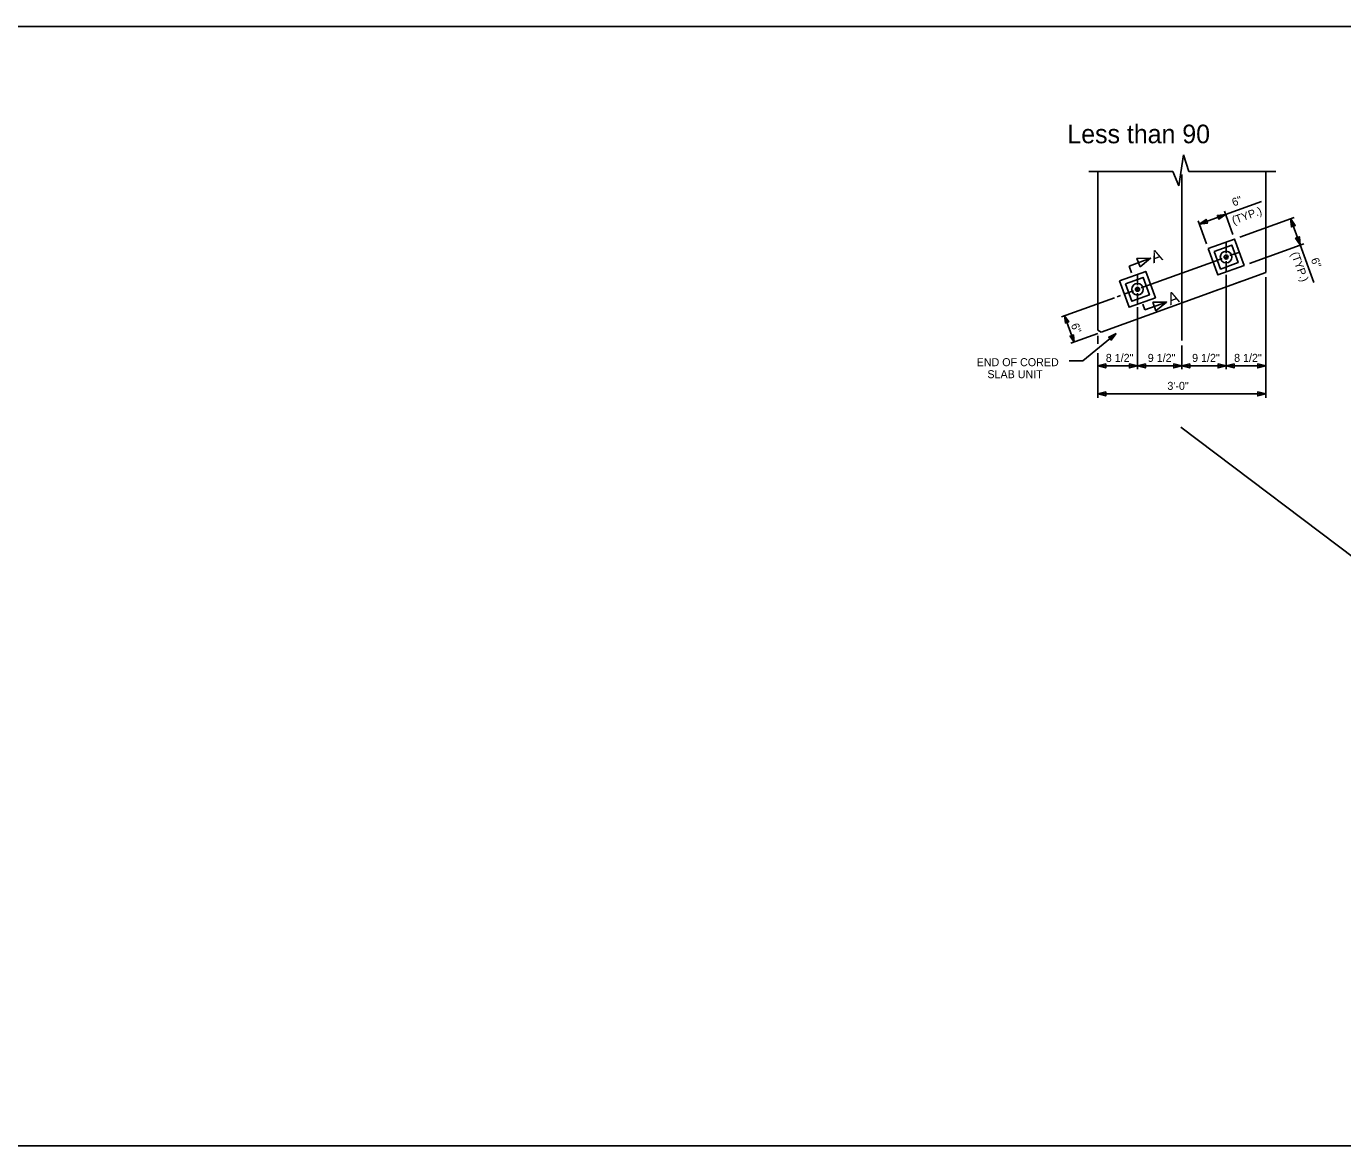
# Model space of a CAD drawing. Extents: x 0 to 177, y -1 to 130.
# Drawn here: x 125.78 to 149.29, y -0.86 to 19.14 of the extents above; entities that cross this region are included whole.
import ezdxf

# ---------------------------------------------------------------- set-up
doc = ezdxf.new("R2010")
doc.units = 0
for name, color, linetype in [('Arrowhead Terminators CELL', 7, 'Continuous'), ('Dimension Lines', 7, 'Continuous'), ('Mis Center Lines', 7, 'Continuous'), ('Plan Sheet', 7, 'Continuous'), ('Rebar Lines', 7, 'Continuous'), ('Structural Steel Lines', 7, 'Continuous'), ('Sup Concrete Girder Lines', 7, 'Continuous'), ('Sup Cored Slab Unit', 7, 'Continuous'), ('Text', 7, 'Continuous'), ('User Information Notes', 7, 'Continuous')]:
    doc.layers.add(name, color=color, linetype=linetype)

msp = doc.modelspace()

# ---------------------------------------------------------------- linework, layer by layer
at = {"layer": 'Arrowhead Terminators CELL'}
for points in [[(147.2, 15.773), (147.078, 15.69), (147.054, 15.757)], [(146.73, 15.602), (146.852, 15.684), (146.876, 15.617)], [(148.362, 15.699), (148.444, 15.577), (148.378, 15.552)], [(148.533, 15.229), (148.451, 15.35), (148.518, 15.375)], [(145.672, 14.837), (145.861, 14.991), (145.618, 14.988)], [(145.903, 14.205), (146.146, 14.208), (145.957, 14.054)], [(145.246, 13.647), (145.159, 13.529), (145.114, 13.584)], [(144.918, 13.068), (145.061, 13.104), (145.061, 13.033)], [(145.627, 13.068), (145.484, 13.033), (145.484, 13.104)], [(145.627, 13.068), (145.769, 13.104), (145.769, 13.033)], [(146.418, 13.068), (146.276, 13.033), (146.276, 13.104)], [(146.418, 13.068), (146.561, 13.104), (146.561, 13.033)], [(147.21, 13.068), (147.068, 13.033), (147.068, 13.104)], [(147.21, 13.068), (147.353, 13.104), (147.353, 13.033)], [(147.918, 13.068), (147.776, 13.033), (147.776, 13.104)], [(144.918, 12.568), (145.061, 12.604), (145.061, 12.533)], [(147.918, 12.568), (147.776, 12.533), (147.776, 12.604)]]:
    msp.add_lwpolyline(points, close=True, dxfattribs=at)
at = {"layer": 'Dimension Lines'}
for p, q in [((147.843, 16.007), (147.2, 15.773)), ((147.2, 15.773), (146.73, 15.602)), ((147.179, 15.83), (147.329, 15.418)), ((146.709, 15.659), (146.859, 15.247)), ((148.425, 15.721), (147.454, 15.368)), ((148.362, 15.699), (148.533, 15.229)), ((147.21, 15.272), (147.21, 15.084)), ((147.455, 15.102), (147.278, 15.038)), ((148.596, 15.252), (147.625, 14.898)), ((148.533, 15.229), (148.777, 14.56)), ((145.476, 14.851), (145.861, 14.991)), ((145.52, 14.73), (145.476, 14.851)), ((147.141, 14.988), (146.965, 14.924)), ((147.21, 14.941), (147.21, 14.754)), ((145.627, 14.696), (145.627, 14.508)), ((147.21, 14.698), (147.21, 13.007)), ((147.918, 14.655), (147.918, 12.497)), ((145.558, 14.412), (145.382, 14.348)), ((145.627, 14.365), (145.627, 14.178)), ((145.872, 14.526), (145.695, 14.462)), ((145.214, 14.286), (144.267, 13.942)), ((145.323, 14.326), (145.264, 14.305)), ((145.627, 14.115), (145.627, 13.007)), ((145.761, 14.068), (145.723, 14.171)), ((145.761, 14.068), (146.146, 14.208)), ((144.325, 13.963), (144.496, 13.493)), ((144.918, 13.647), (144.438, 13.472)), ((145.246, 13.647), (144.651, 13.159)), ((144.918, 13.606), (144.918, 13.463)), ((146.418, 13.433), (146.418, 13.007)), ((144.918, 13.293), (144.918, 12.497)), ((144.651, 13.159), (144.406, 13.159)), ((145.627, 13.068), (144.918, 13.068)), ((146.418, 13.068), (145.627, 13.068)), ((147.21, 13.068), (146.418, 13.068)), ((147.918, 13.068), (147.21, 13.068)), ((147.918, 12.568), (144.918, 12.568))]:
    msp.add_line(p, q, dxfattribs=at)
for points in [[(147.18, 15.002), (147.21, 15.013), (147.21, 14.981)], [(147.24, 15.024), (147.21, 15.013), (147.21, 15.045)], [(145.597, 14.426), (145.627, 14.437), (145.627, 14.405)], [(145.656, 14.448), (145.627, 14.437), (145.627, 14.468)], [(144.368, 13.846), (144.374, 13.848), (144.325, 13.963), (144.38, 13.85), (144.386, 13.852), (144.325, 13.963), (144.392, 13.854), (144.398, 13.856), (144.325, 13.963), (144.339, 13.835), (144.345, 13.837), (144.325, 13.963), (144.351, 13.839), (144.356, 13.841), (144.325, 13.963), (144.362, 13.843), (144.398, 13.856), (144.339, 13.835), (144.325, 13.963), (144.398, 13.856)], [(144.454, 13.611), (144.46, 13.613), (144.496, 13.493), (144.465, 13.615), (144.471, 13.617), (144.496, 13.493), (144.477, 13.619), (144.483, 13.621), (144.496, 13.493), (144.424, 13.6), (144.43, 13.602), (144.496, 13.493), (144.436, 13.604), (144.442, 13.606), (144.496, 13.493), (144.448, 13.609), (144.483, 13.621), (144.424, 13.6), (144.496, 13.493), (144.483, 13.621)]]:
    msp.add_lwpolyline(points, dxfattribs=at)
at = {"layer": 'Mis Center Lines'}
for p, q in [((146.418, 16.49), (146.418, 13.524)), ((145.872, 14.526), (146.965, 14.924))]:
    msp.add_line(p, q, dxfattribs=at)
at = {"layer": 'Plan Sheet'}
for p, q in [((97.47, 19.135), (176.951, 19.135)), ((97.47, -0.865), (176.951, -0.865))]:
    msp.add_line(p, q, dxfattribs=at)
at = {"layer": 'Rebar Lines'}
for centre in [(147.21, 15.013), (145.627, 14.437)]:
    msp.add_circle(centre, 0.0365, dxfattribs=at)
at = {"layer": 'Structural Steel Lines'}
for points in [[(146.996, 15.113), (147.11, 14.799), (147.424, 14.913), (147.31, 15.227)], [(145.413, 14.536), (145.527, 14.223), (145.84, 14.337), (145.726, 14.65)]]:
    msp.add_lwpolyline(points, close=True, dxfattribs=at)
at = {"layer": 'Sup Concrete Girder Lines'}
for p, q in [((146.45, 16.839), (146.365, 16.286)), ((146.546, 16.54), (146.45, 16.839)), ((146.259, 16.54), (144.759, 16.54)), ((144.918, 13.709), (144.918, 16.54)), ((146.365, 16.286), (146.259, 16.54)), ((148.099, 16.54), (146.546, 16.54)), ((147.918, 14.739), (147.918, 16.54)), ((147.918, 14.739), (144.977, 13.668)), ((144.918, 13.709), (144.977, 13.668))]:
    msp.add_line(p, q, dxfattribs=at)
for centre in [(147.21, 15.013), (145.627, 14.437)]:
    msp.add_circle(centre, 0.104, dxfattribs=at)
at = {"layer": 'Sup Cored Slab Unit'}
for points in [[(146.89, 15.163), (147.061, 14.693), (147.53, 14.864), (147.359, 15.334)], [(145.306, 14.586), (145.477, 14.116), (145.947, 14.287), (145.776, 14.757)]]:
    msp.add_lwpolyline(points, close=True, dxfattribs=at)
at = {"layer": 'Text'}
for p, q in [((147.918, 14.81), (147.918, 16.26)), ((147.918, 14.81), (147.918, 15.942)), ((147.918, 14.81), (147.918, 15.807)), ((147.918, 14.81), (147.918, 15.72)), ((147.918, 14.81), (147.918, 15.512)), ((147.079, 14.433), (146.865, 14.355)), ((147.454, 14.57), (147.361, 14.536))]:
    msp.add_line(p, q, dxfattribs=at)
at = {"layer": 'User Information Notes'}
for q in [(146.4, 11.974), (153.4, 6.689)]:
    msp.add_line((146.4, 11.974), q, dxfattribs=at)

# ---------------------------------------------------------------- texts
at = {"layer": 'Dimension Lines'}
for p in [(145.911, 14.899), (146.21, 14.15)]:
    msp.add_text('A', height=0.215, rotation=20.0008, dxfattribs=at).set_placement(p)
at = {"layer": 'Text'}
for s, rotation, p in [('6"', 20.0008, (147.345, 15.916)), ('(TYP.)', 20.0008, (147.344, 15.592)), ('(TYP.)', 290.0008, (148.365, 15.076)), ('6"', 290.0008, (148.721, 14.97)), ('6"', 290.0121, (144.435, 13.801))]:
    msp.add_text(s, height=0.143, rotation=rotation, dxfattribs=at).set_placement(p)
for s, p in [('END OF CORED', (142.754, 13.063)), ('8 1/2"', (145.061, 13.14)), ('9 1/2"', (145.811, 13.14)), ('9 1/2"', (146.603, 13.14)), ('8 1/2"', (147.353, 13.14)), ('SLAB UNIT', (142.946, 12.848)), ('3\'-0"', (146.161, 12.64))]:
    msp.add_text(s, height=0.143, dxfattribs=at).set_placement(p)
at = {"layer": 'User Information Notes'}
msp.add_text('Less than 90', height=0.33267, dxfattribs=at).set_placement((144.375, 17.046))

doc.saveas('drawing.dxf')
